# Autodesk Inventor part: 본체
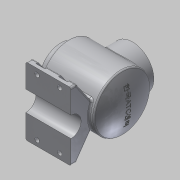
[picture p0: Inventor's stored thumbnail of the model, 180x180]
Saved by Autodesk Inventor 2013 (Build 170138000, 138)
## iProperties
Created: 2017-04
Part Number: 본체
Material: 알루미늄 6061
Document SubType Name: Modeling
Designer: Administrator
Density: 2.71 g/cm^3
Mass: 1670.76 g
Surface Area: 1066.88 cm^2
Volume: 616.516 cm^3
Author: Administrator
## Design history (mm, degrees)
sketch "스케치1"
  geometry: L1 (0, 0)-(120, 0); L2 (0, 28)-(0, 38); L3 (0, 38)-(9, 38); L4 (12, 41)-(12, 47); L5 (15, 50)-(108.336, 50); L6 (1, 27)-(22, 27); L7 (22, 27)-(22, 37); L8 (25, 40)-(99.903, 40); L9 (1, 27)-(0, 28); A1 r 113 centre (7, 0) between (120, 0) and (108.336, 50); A2 r 103 centre (7, 0) between (110, 0) and (102.69, 38.11); A3 r 3 centre (25, 37) between (25, 40) and (22, 37); A4 r 3 centre (99.903, 37) between (102.69, 38.11) and (99.903, 40); A5 r 3 centre (15, 47) between (15, 50) and (12, 47); A6 r 3 centre (9, 41) between (9, 38) and (12, 41); 2 further points
  constraints: 18 end point, 13 point on circle, 8 tangent, 6 centre point, 6 point on line, 4 parallel, 3 equal radius, 3 perpendicular, 1 horizontal
  dimensions: "d0" = 120 distance of L1.start L1.end; "d1" = 226 diameter of A1; "d2" = 10 radial gap between concentric circles of A1 A2; "d4" = 100 diameter of L5 L1; "d5" = 76 diameter of L3 L1; "d6" = 54 diameter of L6 L1; "d7" = 80 diameter of L8 L1; "d8" = 22 distance between parallel lines of L7 L2; "d9" = 12 distance between parallel lines of L4 L2; "d10" = 3 radius of A3; "d11" = 1 distance of L6.start point (0, 27); "d12" = 1 distance of L2.start point (0, 27) (= d11)
revolve "회전1" sketch "스케치1" stored, may be unused: angle "d13" = 90 deg
node "작업 평면1"
sketch "스케치2"
  geometry: C1 r 38 at (-62, 0); 1 further point
  constraints: 1 centre point, 1 horizontal alignment
  dimensions: "d15" = 76 diameter of C1; "d17" = 62 distance of point (0, 0) C1.centre
extrude "돌출1" join sketch "스케치2" stored distance "d18" = 10; taper "d19" = 0 deg
fillet "모깎기1" dims "d20" = 3
sketch "스케치3"
  geometry: C1 r 38 at (0, 0) reference; C2 r 27 at (0, 0); 1 further point
  constraints: 1 centre point, 1 coincident
  dimensions: "d21" = 54 diameter of C2
extrude "돌출2" cut sketch "스케치3" stored distance "d23" = 10; taper "d24" = 0 deg
chamfer "모따기1" distance "d25" = 1; stored, may be unused: second distance "d26" = 2, angle "d27" = 45 deg
sketch "스케치4"
  geometry: C1 r 38 at (0, 0) reference; 1 further point
  constraints: 1 vertical alignment
  dimensions: "d28" = 32.5 distance of C1.centre point (0, 32.5)
hole "구멍1" sketch "스케치4" at (0, 32.5) diameter "d29" = 3.242; stored, may be unused: countersink angle "d33" = 90 deg, drill point angle "d35" = 118 deg; dims "d30" = 8, "d31" = 4, "d32" = 2, "d34" = 10
sketch "스케치5"
  geometry: C1 r 38 at (0, 0) reference; 2 further points
  constraints: 1 vertical alignment
  dimensions: "d39" = 32.5 distance of C1.centre point (0, 32.5)
hole "구멍2" sketch "스케치5" at (0, 32.5) diameter "d40" = 3.242; stored, may be unused: countersink angle "d44" = 90 deg, drill point angle "d46" = 118 deg; dims "d41" = 8, "d42" = 4, "d43" = 2, "d45" = 10
node "작업 평면2"
sketch "스케치6"
  geometry: L1 (-20, 60)-(-100, 60); L2 (-100, 60)-(-100, -60); L3 (-100, -60)-(-20, -60); L4 (-20, -60)-(-20, 60); L5 (-20, 60)-(-100, -60); L6 (-100, 60)-(-20, -60); L7 (-12, 47)-(-12, -47) reference; 1 further point
  constraints: 12 end point, 2 parallel, 1 horizontal, 1 perpendicular
  dimensions: "d54" = 120 distance of L3.end L1.start; "d56" = 80 distance of L2.end L3.end; "d92" = 8 distance between parallel lines of L4 L7; "d93" = 60 distance from line of point (0, 0) L1
extrude "돌출3" join sketch "스케치6" distance "d57" = 10; taper "d58" = 0 deg
sketch "스케치7"
  geometry: L1 (120, 0)-(120, 10) reference; L2 (0, 10)-(120, 10) reference; L3 (0, 0)-(0, 10) reference; L4 (0, 10)-(38.416, 36.899); L5 (120, 10)-(81.584, 36.899); A1 r 50 centre (60, 82) between (38.416, 36.899) and (81.584, 36.899) reference; 1 further point
  constraints: 4 end point, 2 point on circle
  dimensions: "d59" = 55 deg angle of L3 L4; "d60" = 55 deg angle of L1 L5
extrude "돌출4" join sketch "스케치7" distance "d61" = 80; taper "d62" = 0 deg
fillet "모깎기2" dims "d63" = 3
fillet "모깎기3" dims "d64" = 3
sketch "스케치8"
  geometry: L1 (0, 0)-(114, 0) reference; C1 r 18 at (57, 0); A1 r 50 centre (57, 82) between (38.639, 35.493) and (75.361, 35.493) reference
  constraints: 1 centre point, 1 midpoint, 1 vertical alignment
  dimensions: "d65" = 36 diameter of C1
extrude "돌출5" cut sketch "스케치8" distance "d67" = 80; taper "d68" = 0 deg
sketch "스케치9"
  geometry: L1 (20, 18)-(20, 57) reference; C1 r 4 at (40, 50); 2 further points
  constraints: 1 centre point
  dimensions: "d71" = 8 diameter of C1; "d73" = 50 vertical distance of point (62, 0) C1.centre; "d94" = 20 distance from line of C1.centre L1
extrude "돌출6" cut sketch "스케치9" distance "d75" = 6; taper "d76" = 0 deg
sketch "스케치10"
  geometry: L1 (-8, 0)-(-8, 10); L2 (-17, 10)-(57, 10) reference; L3 (-17, 10)-(57, 10) reference; L4 (8, 0)-(8, 10); C1 r 4 at (0, 0) reference; A1 r 8 centre (0, 0) between (-8, 0) and (8, 0); 1 further point
  constraints: 4 end point, 2 point on circle, 2 point on line, 2 tangent, 1 centre point, 1 coincident, 1 perpendicular, 1 vertical
  dimensions: "d77" = 16 diameter of A1
extrude "돌출7" cut sketch "스케치10" stored distance "d79" = 6; taper "d80" = 0 deg
node "작업 평면3"
sketch "스케치11"
  geometry: L1 (4.803, 33.183)-(4.803, -33.183); L2 (4.803, -33.183)-(-4.803, -33.183); L3 (-4.803, -33.183)-(-4.803, 33.183); L4 (-4.803, 33.183)-(4.803, 33.183); L5 (0, 33.183)-(0, -33.183); L6 (4.803, 0)-(-4.803, 0); 1 further point
  constraints: 6 midpoint, 4 end point, 2 other
feature "엠보싱1" sketch "스케치11" dims "d88" = 0.5, "d89" = 0
fillet "모깎기4" dims "d90" = 3
fillet "모깎기5" dims "d91" = 3
node "솔리드1"
pattern_circular "원형 패턴1" dims angle "d37" = 360 deg
pattern_circular "원형 패턴2" dims angle "d48" = 360 deg
pattern_linear "직사각형 패턴1" dims "d86" = 1
mirror "대칭1"
node "투영된 루프1"
other parameters: "d14" = 65, "d50" = -82
